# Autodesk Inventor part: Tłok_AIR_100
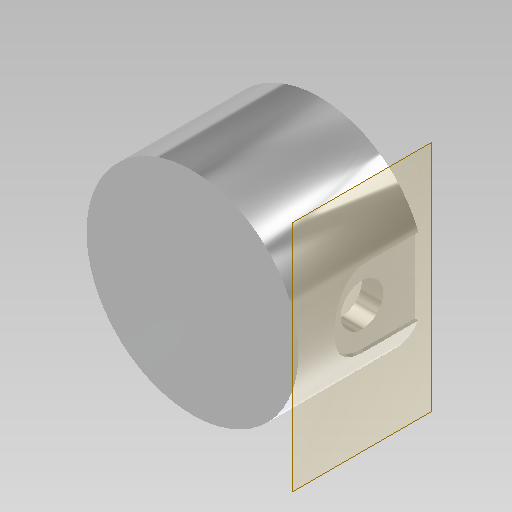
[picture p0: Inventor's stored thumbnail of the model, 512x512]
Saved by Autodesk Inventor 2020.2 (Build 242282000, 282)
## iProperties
Created: 2014-10
Part Number: Tłok_AIR_100
Material: Aluminium 6061
Document SubType Name: Modeling
Designer: F.Stasiak
Density: 2.7 g/cm^3
Appearance: Aluminium - płaski
Mass: 581.534 g
Surface Area: 472.587 cm^2
Volume: 215.383 cm^3
Catalog Web Link: www.expertbooks.pl
Manager: www.cadconsulting.pl
Company: Fabian Stasiak CAD Consulting
Author: F.Stasiak
Subject: Zbiór ćwiczeń. Autodesk Inventor 2020. Kurs Professional
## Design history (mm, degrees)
sketch "Szkic1"
  geometry: C1 r 50 at (0, 0); 1 further point
  constraints: 1 centre point, 1 coincident
  dimensions: "d0" = 100 diameter of C1
extrude "Wyciągnięcie proste1" new body sketch "Szkic1" distance "d1" = 60; taper "d2" = 0 deg
node "Płaszczyzna konstrukcyjna1"
sketch "Szkic2"
  geometry: L1 (-50, 0)-(50, 0) reference; L2 (18, 25)-(18, 0); L3 (-18, 25)-(-18, 0); A1 r 18 centre (0, 25) between (18, 25) and (-18, 25); 1 further point
  constraints: 4 end point, 2 point on circle, 2 point on line, 2 tangent, 1 centre point, 1 perpendicular, 1 vertical
  dimensions: "d3" = 36 diameter of A1; "d4" = 25 distance of L3.start L3.end
extrude "Wyciągnięcie proste2" cut sketch "Szkic2" distance "d5" = 5; taper "d6" = 0 deg
mirror "Odbicie lustrzane1"
feature "Skorupa1" dims "d7" = 10
sketch "Szkic3"
  geometry: C1 r 10 at (-25, 0); A1 r 18 centre (-25, 0) between (-25, 18) and (-25, -18) reference; 1 further point
  constraints: 1 centre point, 1 coincident
  dimensions: "d8" = 20 diameter of C1
extrude "Wyciągnięcie proste3" cut sketch "Szkic3" extent not by distance; stored distance "d9" = 5; taper "d10" = 0 deg
node "Bryła1"
